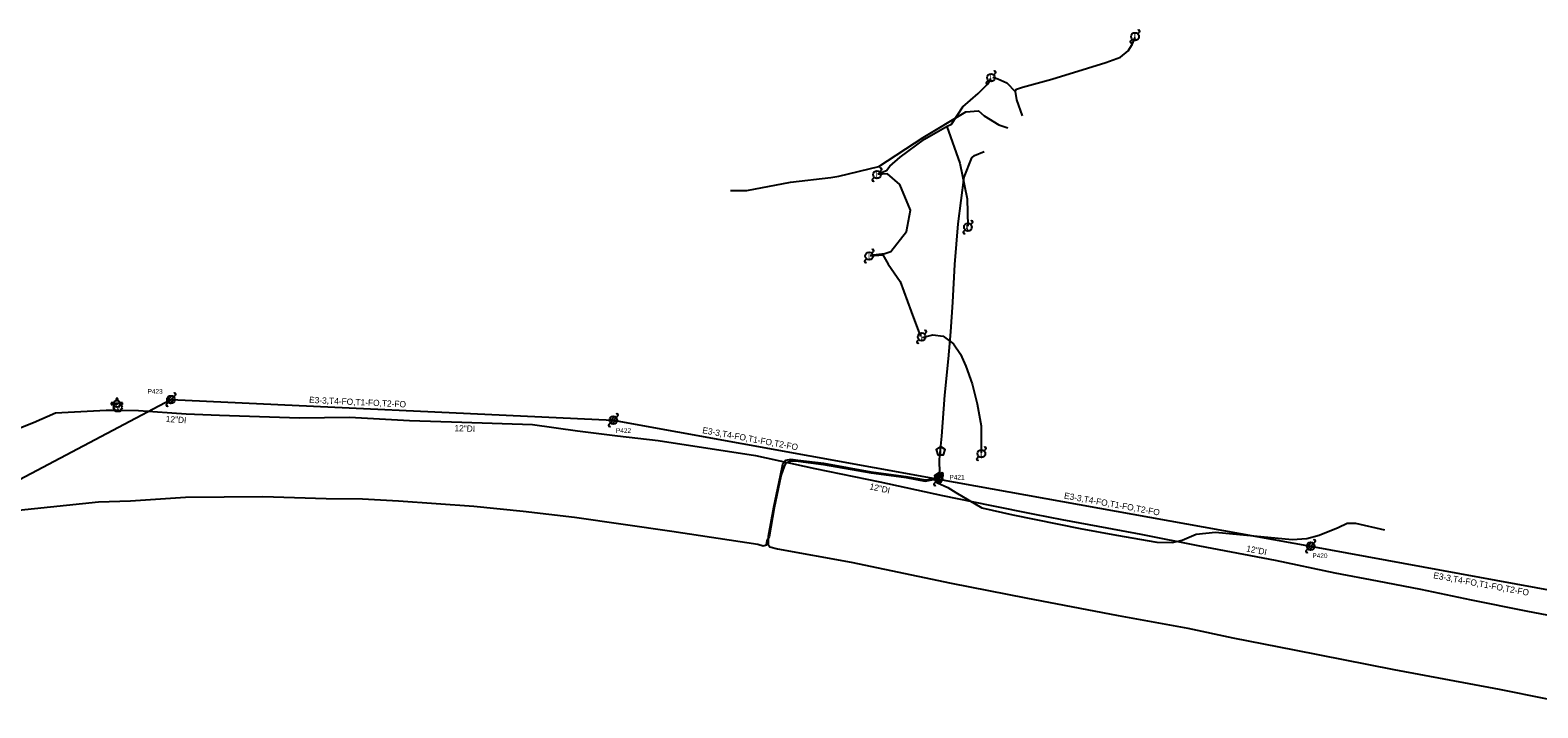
# Model space of a CAD drawing. Extents: x 1741604 to 1825760, y 1164229 to 1194908.
# Drawn here: x 1818146 to 1819111, y 1191865 to 1192299 of the extents above; entities that cross this region are included whole.
import ezdxf

# ---------------------------------------------------------------- set-up
doc = ezdxf.new("R2010")
doc.units = 0
for name, color, linetype in [('RD_EX_SU_Elec', 7, 'Continuous'), ('RD_EX_SU_H2O', 7, 'Continuous'), ('RD_EX_SU_Ovhd', 7, 'Continuous'), ('RD_EX_SU_Pole', 7, 'Continuous'), ('RD_EX_SU_Telecom', 7, 'Continuous'), ('RD_EX_SU_TX_H2O', 7, 'Continuous'), ('RD_EX_SU_TX_Pole', 7, 'Continuous')]:
    doc.layers.add(name, color=color, linetype=linetype)

# ---------------------------------------------------------------- blocks, each defined once
blk = doc.blocks.new('SUE_WV')
at = {"layer": 'RD_EX_SU_H2O'}
blk.add_lwpolyline([(2.89, 0), (1.44, 2.5), (-1.44, 2.5), (-2.89, 0), (-1.44, -2.5), (1.44, -2.5)], close=True, dxfattribs=at)
blk.add_text('V', height=3.75, dxfattribs=at).set_placement((-1.43, -1.88))
blk = doc.blocks.new('SUE_WFH')
at = {"layer": 'RD_EX_SU_H2O'}
for p, q in [((-2.01, 0.6), (-3.65, 0.6)), ((-3.65, 0.6), (-3.65, -0.45)), ((-0.48, 3.38), (-0.48, 2.04)), ((0.57, 3.38), (-0.48, 3.38)), ((0.57, 2.02), (0.57, 3.38)), ((3.7, 0.6), (2.01, 0.6)), ((3.7, -0.45), (3.7, 0.6)), ((-3.65, -0.45), (-2.05, -0.45)), ((2.05, -0.45), (3.7, -0.45))]:
    blk.add_line(p, q, dxfattribs=at)
for radius in [2.1, 0.263]:
    blk.add_circle((0, 0), radius, dxfattribs=at)
for start, end in [(163.3387, 192.31502), (74.24552, 103.21276), (347.68498, 16.6613)]:
    blk.add_arc((0, 0), 2.1, start, end, dxfattribs=at)
blk = doc.blocks.new('SUE_POP')
at = {"layer": 'RD_EX_SU_Pole'}
for p, q in [((1.77, 1.77), (2.83, 2.83)), ((-2.83, -2.83), (-1.77, -1.77))]:
    blk.add_line(p, q, dxfattribs=at)
blk.add_circle((0, 0), 2.5, dxfattribs=at)
for centre, start, end in [((2.3, 3.36), 315, 135), ((-2.3, -3.36), 135, 315)]:
    blk.add_arc(centre, 0.75, start, end, dxfattribs=at)
blk.add_text('O', height=4, dxfattribs=at).set_placement((-1.53, -2))

msp = doc.modelspace()

# ---------------------------------------------------------------- linework, layer by layer
at = {"layer": 'RD_EX_SU_Elec'}
for points in [[(1818776.82, 1192259.38), (1818777.65, 1192260.84), (1818781.42, 1192262.15), (1818800.2, 1192267.31), (1818823.06, 1192274.26), (1818834.94, 1192277.93), (1818844.17, 1192281.27), (1818849.07, 1192285.29), (1818851.69, 1192289.37), (1818853.69, 1192293.9)], [(1818688.93, 1192206.72), (1818694.4, 1192208.68), (1818696.57, 1192211.56), (1818703.15, 1192217.33), (1818718.79, 1192228.88), (1818733.32, 1192237.13), (1818736.01, 1192238.41), (1818743.34, 1192249.59), (1818753.17, 1192258.14), (1818760.01, 1192264.88), (1818761.13, 1192267.75)], [(1818762.45, 1192268.54), (1818765.71, 1192267.41), (1818771.42, 1192264.99), (1818776.82, 1192259.38), (1818777.68, 1192254.06), (1818781.3, 1192243.72)], [(1818594.62, 1192196.08), (1818605.04, 1192195.88), (1818633.01, 1192201.33), (1818658.8, 1192204.33), (1818663.91, 1192205.09), (1818689.59, 1192211.37), (1818717.99, 1192229.82), (1818745.26, 1192246.37), (1818753.32, 1192246.98), (1818756.95, 1192243.77), (1818766.37, 1192237.94), (1818772.16, 1192235.99)], [(1818733.06, 1192236.99), (1818741.29, 1192213.56), (1818746, 1192190.55), (1818746.48, 1192173.06)], [(1818684.04, 1192154.55), (1818693.32, 1192155.71), (1818697.17, 1192156.88), (1818707.29, 1192169.71), (1818709.73, 1192183.32), (1818702.95, 1192199.75), (1818694.99, 1192206.7), (1818688.96, 1192206.28)], [(1818684.09, 1192154.23), (1818692.07, 1192154.72), (1818695.45, 1192148.88), (1818703.28, 1192137.79), (1818710.31, 1192118.59), (1818716.1, 1192102.47)], [(1818717.43, 1192101.78), (1818724.01, 1192103.58), (1818730.61, 1192102.62), (1818737.31, 1192097.84), (1818741.85, 1192091.19), (1818745.29, 1192083.57), (1818749.19, 1192072.21), (1818752.42, 1192059.33), (1818755.06, 1192045.41), (1818754.97, 1192028.11)]]:
    msp.add_lwpolyline(points, dxfattribs=at)
at = {"layer": 'RD_EX_SU_H2O'}
for points in [[(1818122.59, 1192037.5), (1818148.22, 1192047.45), (1818162.29, 1192053.75), (1818170.57, 1192054.1), (1818194.86, 1192055.44), (1818203.13, 1192055.37), (1818215.62, 1192055.06), (1818246.05, 1192052.91), (1818267.39, 1192052.06)], [(1818267.39, 1192052.06), (1818318.67, 1192050.36), (1818350.7, 1192050.9), (1818388.95, 1192048.7), (1818422.44, 1192047.76), (1818467.76, 1192046.22), (1818496.6, 1192042.15), (1818522.17, 1192039.02)], [(1818522.17, 1192039.02), (1818548.17, 1192035.97), (1818610.63, 1192026.34), (1818648.53, 1192017.92), (1818690.14, 1192009.37), (1818730.37, 1192000.7), (1818760.55, 1191994.59), (1818789.24, 1191988.71), (1818806.7, 1191985.31), (1818835.47, 1191980.1), (1818857.19, 1191976.03), (1818894.89, 1191968.58), (1818943.24, 1191959.34), (1818981.38, 1191951.29), (1819008.54, 1191946), (1819036.35, 1191940.71), (1819068.78, 1191933.94), (1819103.79, 1191926.89), (1819147.33, 1191918.52)]]:
    msp.add_lwpolyline(points, dxfattribs=at)
at = {"layer": 'RD_EX_SU_Ovhd'}
for p, q in [((1818042.36, 1191959.98), (1818236.29, 1192062.12)), ((1818236.29, 1192062.12), (1818519.53, 1192048.91)), ((1818519.53, 1192048.91), (1818727.68, 1192011.23)), ((1818727.68, 1192011.23), (1818965.98, 1191968.33)), ((1818965.98, 1191968.33), (1819213.81, 1191922.61))]:
    msp.add_line(p, q, dxfattribs=at)
at = {"layer": 'RD_EX_SU_Pole'}
for p, q in [((1818855.35, 1192296.28), (1818856.41, 1192297.34)), ((1818850.75, 1192291.68), (1818851.81, 1192292.74)), ((1818758.51, 1192265.42), (1818759.57, 1192266.48)), ((1818763.1, 1192270.01), (1818764.17, 1192271.07)), ((1818690.07, 1192207.91), (1818691.13, 1192208.97)), ((1818685.47, 1192203.31), (1818686.53, 1192204.37)), ((1818743.72, 1192169.69), (1818744.79, 1192170.75)), ((1818748.32, 1192174.29), (1818749.38, 1192175.35)), ((1818680.51, 1192151.19), (1818681.57, 1192152.25)), ((1818685.11, 1192155.79), (1818686.17, 1192156.85)), ((1818718.72, 1192104.04), (1818719.78, 1192105.1)), ((1818714.13, 1192099.45), (1818715.19, 1192100.51)), ((1818233.88, 1192061.47), (1818236.94, 1192064.54)), ((1818234.52, 1192060.35), (1818238.06, 1192063.89)), ((1818235.64, 1192059.71), (1818238.7, 1192062.77)), ((1818238.06, 1192063.89), (1818239.12, 1192064.95)), ((1818233.46, 1192059.29), (1818234.52, 1192060.35)), ((1818516.7, 1192046.09), (1818517.76, 1192047.15)), ((1818517.12, 1192048.27), (1818520.18, 1192051.33)), ((1818517.76, 1192047.15), (1818521.3, 1192050.68)), ((1818518.88, 1192046.5), (1818521.95, 1192049.56)), ((1818521.3, 1192050.68), (1818522.36, 1192051.74)), ((1818752.37, 1192024.68), (1818753.43, 1192025.74)), ((1818756.96, 1192029.28), (1818758.02, 1192030.34)), ((1818729.45, 1192012.99), (1818730.51, 1192014.06)), ((1818724.86, 1192008.4), (1818725.92, 1192009.46)), ((1818725.27, 1192010.58), (1818728.33, 1192013.64)), ((1818725.92, 1192009.46), (1818729.45, 1192012.99)), ((1818727.04, 1192008.81), (1818730.1, 1192011.87)), ((1818963.15, 1191965.5), (1818964.21, 1191966.56)), ((1818963.56, 1191967.68), (1818966.63, 1191970.74)), ((1818964.21, 1191966.56), (1818967.75, 1191970.1)), ((1818965.33, 1191965.91), (1818968.39, 1191968.98)), ((1818967.75, 1191970.1), (1818968.81, 1191971.16))]:
    msp.add_line(p, q, dxfattribs=at)
for centre in [(1818853.58, 1192294.51), (1818761.34, 1192268.24), (1818688.3, 1192206.14), (1818746.55, 1192172.52), (1818683.34, 1192154.02), (1818716.96, 1192102.28), (1818236.29, 1192062.12), (1818519.53, 1192048.91), (1818755.19, 1192027.51), (1818727.68, 1192011.23), (1818965.98, 1191968.33)]:
    msp.add_circle(centre, 2.5, dxfattribs=at)
for centre, start, end in [((1818855.88, 1192297.87), 315, 135), ((1818851.28, 1192291.15), 135, 315), ((1818759.04, 1192264.89), 135, 315), ((1818763.64, 1192271.6), 315, 135), ((1818690.6, 1192209.5), 315, 135), ((1818686, 1192202.78), 135, 315), ((1818744.26, 1192169.16), 135, 315), ((1818748.85, 1192175.88), 315, 135), ((1818681.04, 1192150.66), 135, 315), ((1818685.64, 1192157.38), 315, 135), ((1818719.25, 1192105.64), 315, 135), ((1818714.66, 1192098.92), 135, 315), ((1818238.59, 1192065.48), 315, 135), ((1818233.99, 1192058.76), 135, 315), ((1818521.83, 1192052.27), 315, 135), ((1818517.23, 1192045.55), 135, 315), ((1818752.9, 1192024.15), 135, 315), ((1818757.49, 1192030.87), 315, 135), ((1818729.98, 1192014.59), 315, 135), ((1818725.39, 1192007.87), 135, 315), ((1818968.28, 1191971.69), 315, 135), ((1818963.68, 1191964.97), 135, 315)]:
    msp.add_arc(centre, 0.75, start, end, dxfattribs=at)
at = {"layer": 'RD_EX_SU_Telecom'}
for points in [[(1818728.52, 1192014.65), (1818728.33, 1192023.77), (1818729.86, 1192038.64), (1818731.86, 1192064.94), (1818734.11, 1192088.15), (1818735.7, 1192105.52), (1818736.98, 1192124.39), (1818738.2, 1192148.62), (1818740.28, 1192174.65), (1818744.2, 1192204.49), (1818748.96, 1192216.94), (1818750.83, 1192218.38), (1818756.9, 1192220.9)], [(1818727.79, 1192012.98), (1818724.25, 1192011.27), (1818719.47, 1192010.56), (1818706.98, 1192012.58), (1818684.59, 1192015.71), (1818654.32, 1192021.12), (1818637.65, 1192023.19), (1818633.23, 1192023.67), (1818629.78, 1192023.09), (1818627.9, 1192020.55), (1818626.37, 1192013.4), (1818622.14, 1191993.01), (1818618.6, 1191974.53), (1818618.74, 1191971.95), (1818618.76, 1191969.37), (1818619.76, 1191967.84), (1818624.63, 1191966.53), (1818671.89, 1191958.08), (1818735.77, 1191944.66), (1818783.59, 1191935.16), (1818842.84, 1191923.93), (1818887.35, 1191915.7), (1818916.07, 1191909.53), (1818955.5, 1191901.93), (1819019.23, 1191889.3), (1819086.58, 1191876.65), (1819146.11, 1191864.8)], [(1818138.7, 1191991.3), (1818189.88, 1191996.77), (1818210.39, 1191997.4), (1818245.52, 1191999.76), (1818295.03, 1192000.18), (1818335.69, 1191998.84), (1818358.85, 1191998.67), (1818382.04, 1191997.23), (1818430.2, 1191993.82), (1818461.7, 1191990.8), (1818494.58, 1191986.79), (1818556.96, 1191977.93), (1818612.09, 1191969.52), (1818615.41, 1191968.4), (1818617.67, 1191969.23), (1818617.99, 1191971.91), (1818619.43, 1191974.51), (1818622.68, 1191992.97), (1818626.94, 1192013.27), (1818629.27, 1192019.88), (1818630.42, 1192021.82), (1818633.44, 1192022.98), (1818637.79, 1192022.67), (1818654.19, 1192020.57), (1818684.63, 1192015.25), (1818706.98, 1192012.17), (1818719.24, 1192009.98), (1818724.55, 1192010.92), (1818727.36, 1192012.31)], [(1818727.69, 1192012.15), (1818726.4, 1192010.57), (1818727.16, 1192008.92), (1818733.59, 1192005.81), (1818738.8, 1192002.75), (1818755.47, 1191992.83), (1818775.39, 1191988.44), (1818818.35, 1191979.61), (1818841.6, 1191975.35), (1818867.56, 1191970.77), (1818877.52, 1191970.57), (1818883.75, 1191972.23), (1818892.65, 1191975.93), (1818904.98, 1191977.18), (1818954.08, 1191972.46), (1818963.56, 1191973.16), (1818971.38, 1191975.31), (1818983.67, 1191980.29), (1818989.43, 1191982.94), (1818994.67, 1191983.05), (1819013.29, 1191978.73)]]:
    msp.add_lwpolyline(points, dxfattribs=at)
for points in [[(1818729.07, 1192032.2), (1818726.21, 1192030.13), (1818727.3, 1192026.77), (1818730.83, 1192026.77), (1818731.92, 1192030.13)], [(1818727.9, 1192015.55), (1818725.05, 1192013.48), (1818726.14, 1192010.13), (1818729.67, 1192010.13), (1818730.76, 1192013.48)]]:
    msp.add_lwpolyline(points, close=True, dxfattribs=at)

# ---------------------------------------------------------------- block references
at = {"layer": 'RD_EX_SU_H2O'}
for name, p in [('SUE_WFH', (1818201.65, 1192059.39)), ('SUE_WV', (1818202.29, 1192057.14))]:
    msp.add_blockref(name, p, dxfattribs=at)
at = {"layer": 'RD_EX_SU_Pole'}
msp.add_blockref('SUE_POP', (1818746.55, 1192172.52), dxfattribs=at)

# ---------------------------------------------------------------- texts
at = {"layer": 'RD_EX_SU_Ovhd'}
for rotation, p in [(357.3303, (1818324.68, 1192060)), (349.73767, (1818576.29, 1192040.67)), (349.79476, (1818807.86, 1191998.83)), (349.54676, (1819044.28, 1191947.78))]:
    msp.add_text('E3-3,T4-FO,T1-FO,T2-FO', height=4, rotation=rotation, dxfattribs=at).set_placement(p)
at = {"layer": 'RD_EX_SU_Pole'}
for p in [(1818852.72, 1192292.51), (1818760.47, 1192266.24), (1818687.44, 1192204.14), (1818745.69, 1192170.52), (1818682.48, 1192152.02), (1818716.09, 1192100.28), (1818754.33, 1192025.51)]:
    msp.add_text('L', height=4, dxfattribs=at).set_placement(p)
at = {"layer": 'RD_EX_SU_Telecom'}
for p in [(1818727.81, 1192027.32), (1818726.65, 1192010.68)]:
    msp.add_text('T', height=3.75, dxfattribs=at).set_placement(p)
at = {"layer": 'RD_EX_SU_TX_H2O'}
for rotation, p in [(355.96776, (1818232.86, 1192047.83)), (358.05898, (1818417.77, 1192041.91)), (347.83677, (1818683.28, 1192004.71)), (349.18232, (1818924.51, 1191964.95))]:
    msp.add_text('12"DI', height=4, rotation=rotation, dxfattribs=at).set_placement(p)
at = {"layer": 'RD_EX_SU_TX_Pole'}
for s, p in [('P423', (1818221.35, 1192065.87)), ('P422', (1818521.22, 1192040.78)), ('P421', (1818734.75, 1192010.93)), ('P420', (1818967.09, 1191960.7))]:
    msp.add_text(s, height=3, dxfattribs=at).set_placement(p)

doc.saveas('drawing.dxf')
